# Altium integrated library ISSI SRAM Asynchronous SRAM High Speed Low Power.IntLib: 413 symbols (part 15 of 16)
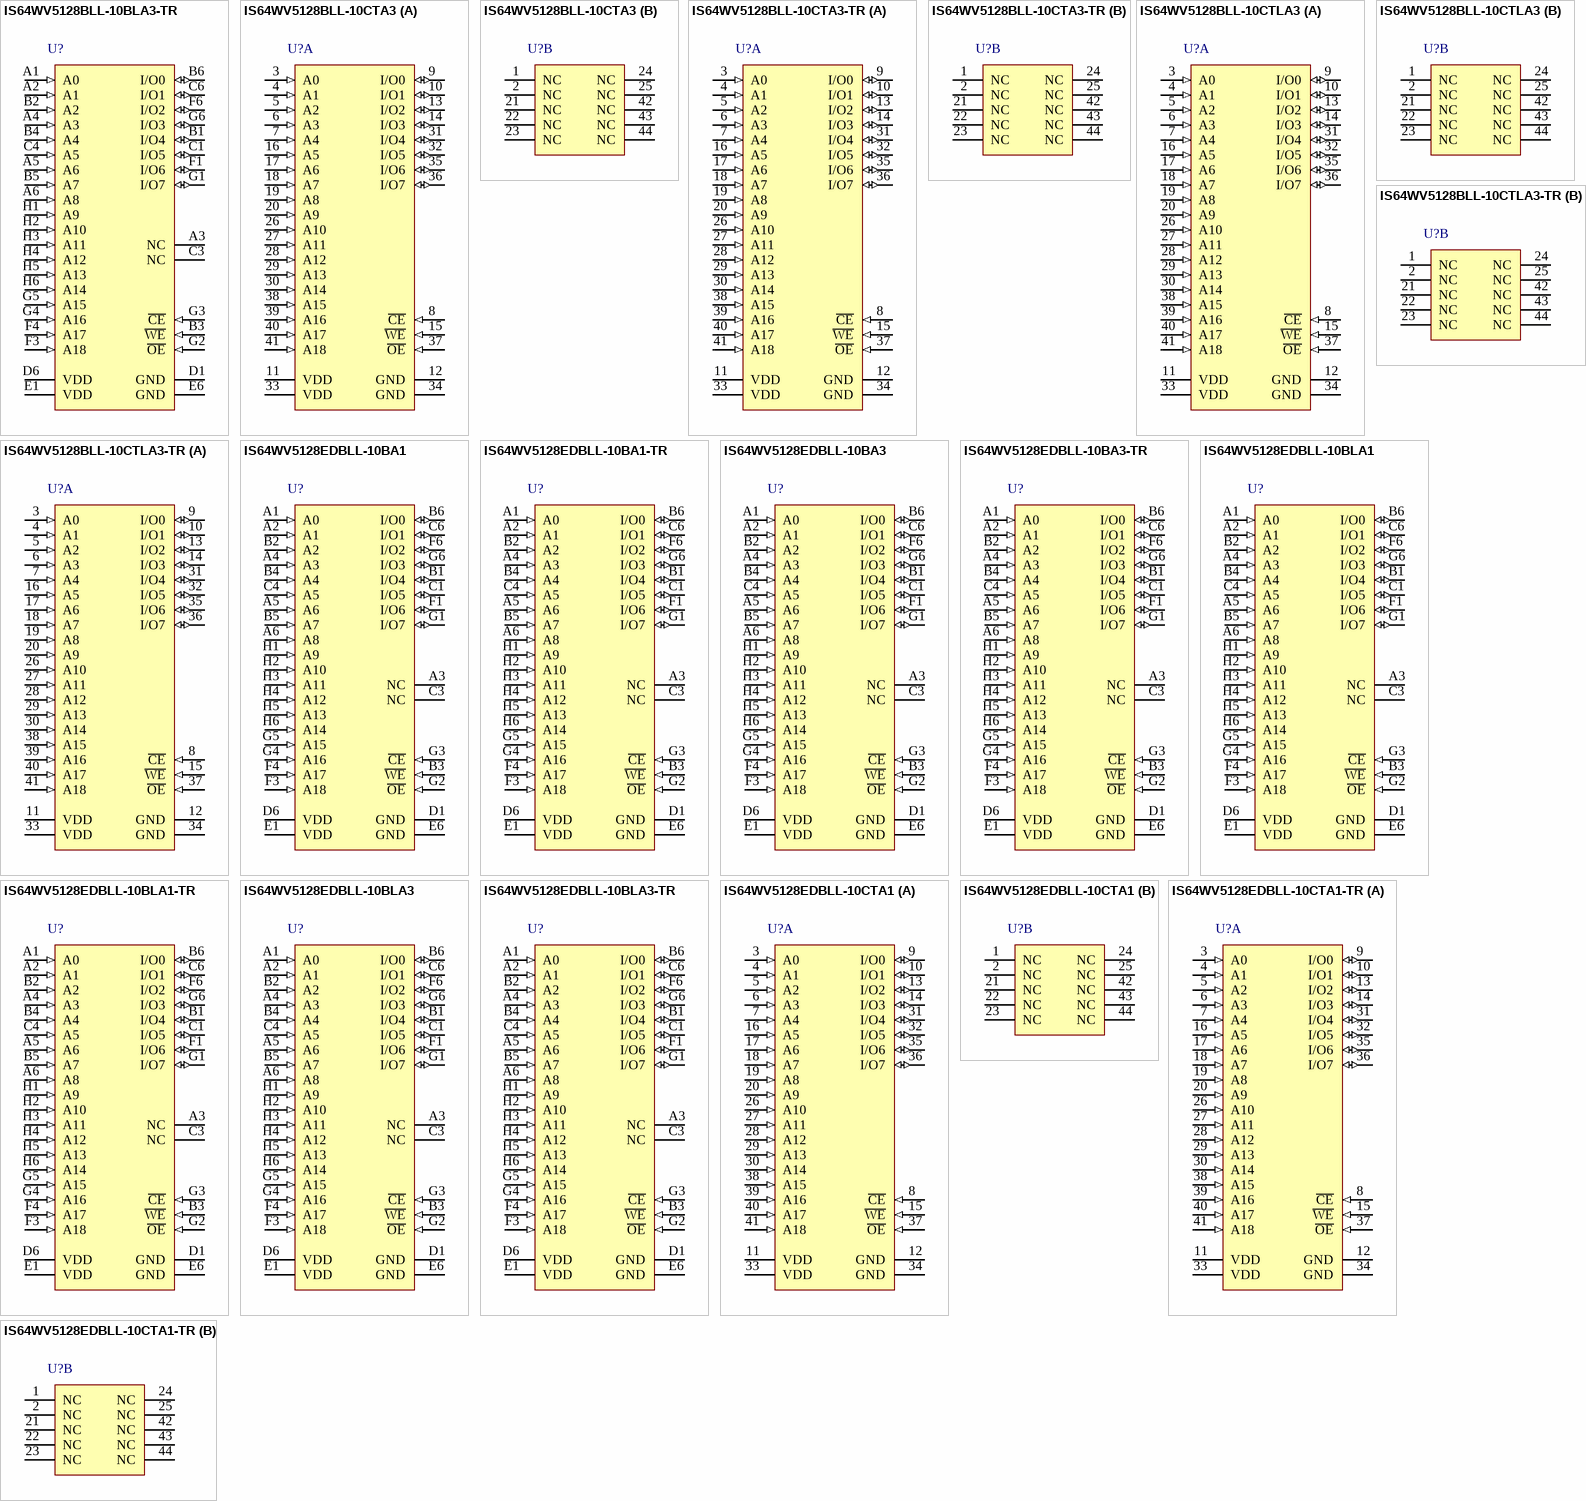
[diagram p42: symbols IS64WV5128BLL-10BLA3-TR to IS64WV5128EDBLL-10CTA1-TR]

## IS64WV5128BLL-10CTLA3-TR
designator U?
4 M High Speed Asynchronous CMOS SRAM, 512 K x 8, -40 to 125 degC, 44-Pin SOP (TSOP-2-44), Pb-Free; Manufacturer: Integrated Silicon Solution Inc (ISSI); PartNumber: IS64WV5128BLL-10CTLA3-TR; Density: 4M; Organization: 512K x 8; Packing: Tape & Reel; Speed (ns): 10
footprint ISSI-TSOP-2-44_N (SOP, 44-Leads, Body 18.5x10.3mm, Pitch 0.8mm, IPC Medium Density)
part A pins: 3 A0 (in) "Address Input", 4 A1 (in) "Address Input", 5 A2 (in) "Address Input", 6 A3 (in) "Address Input", 7 A4 (in) "Address Input", 8 ~{CE} (in) "Chip Enable Input", 9 I/O0 (io) "Bidirectional Port", 10 I/O1 (io) "Bidirectional Port", 11 VDD (power) "Power", 12 GND (power) "Ground", 13 I/O2 (io) "Bidirectional Port", 14 I/O3 (io) "Bidirectional Port", 15 ~{WE} (in) "Write Enable Input", 16 A5 (in) "Address Input", 17 A6 (in) "Address Input", 18 A7 (in) "Address Input", 19 A8 (in) "Address Input", 20 A9 (in) "Address Input", 26 A10 (in) "Address Input", 27 A11 (in) "Address Input", 28 A12 (in) "Address Input", 29 A13 (in) "Address Input", 30 A14 (in) "Address Input", 31 I/O4 (io) "Bidirectional Port", 32 I/O5 (io) "Bidirectional Port", 33 VDD (power) "Power", 34 GND (power) "Ground", 35 I/O6 (io) "Bidirectional Port", 36 I/O7 (io) "Bidirectional Port", 37 ~{OE} (in) "Output Enable Input", 38 A15 (in) "Address Input", 39 A16 (in) "Address Input", 40 A17 (in) "Address Input", 41 A18 (in) "Address Input"
part B pins: 1 NC "No Connection", 2 NC "No Connection", 21 NC "No Connection", 22 NC "No Connection", 23 NC "No Connection", 24 NC "No Connection", 25 NC "No Connection", 42 NC "No Connection", 43 NC "No Connection", 44 NC "No Connection"

## IS64WV5128EDBLL-10BA1
designator U?
4 M High Speed Asynchronous CMOS SRAM with ECC, 512 K x 8, -40 to 85 degC, 36-Pin BGA (TF-BGA-36); Manufacturer: Integrated Silicon Solution Inc (ISSI); PartNumber: IS64WV5128EDBLL-10BA1; Density: 4M; Organization: 512K x 8; Packing: Tray / Tube; Speed (ns): 10
footprint ISSI-TF-BGA-36-6000x8000DE (BGA, 36-Balls, Body 8x6mm, Pitch 0.75mm)
pins: A1 A0 (in) "Address Input", A2 A1 (in) "Address Input", A3 NC "No Connection", A4 A3 (in) "Address Input", A5 A6 (in) "Address Input", A6 A8 (in) "Address Input", B1 I/O4 (io) "Bidirectional Port", B2 A2 (in) "Address Input", B3 ~{WE} (in) "Write Enable Input", B4 A4 (in) "Address Input", B5 A7 (in) "Address Input", B6 I/O0 (io) "Bidirectional Port", C1 I/O5 (io) "Bidirectional Port", C3 NC "No Connection", C4 A5 (in) "Address Input", C6 I/O1 (io) "Bidirectional Port", D1 GND (power) "Ground", D6 VDD (power) "Power", E1 VDD (power) "Power", E6 GND (power) "Ground", F1 I/O6 (io) "Bidirectional Port", F3 A18 (in) "Address Input", F4 A17 (in) "Address Input", F6 I/O2 (io) "Bidirectional Port", G1 I/O7 (io) "Bidirectional Port", G2 ~{OE} (in) "Output Enable Input", G3 ~{CE} (in) "Chip Enable Input", G4 A16 (in) "Address Input", G5 A15 (in) "Address Input", G6 I/O3 (io) "Bidirectional Port", H1 A9 (in) "Address Input", H2 A10 (in) "Address Input", H3 A11 (in) "Address Input", H4 A12 (in) "Address Input", H5 A13 (in) "Address Input", H6 A14 (in) "Address Input"

## IS64WV5128EDBLL-10BA1-TR
designator U?
4 M High Speed Asynchronous CMOS SRAM with ECC, 512 K x 8, -40 to 85 degC, 36-Pin BGA (TF-BGA-36); Manufacturer: Integrated Silicon Solution Inc (ISSI); PartNumber: IS64WV5128EDBLL-10BA1-TR; Density: 4M; Organization: 512K x 8; Packing: Tape & Reel; Speed (ns): 10
footprint ISSI-TF-BGA-36-6000x8000DE (BGA, 36-Balls, Body 8x6mm, Pitch 0.75mm)
pins: A1 A0 (in) "Address Input", A2 A1 (in) "Address Input", A3 NC "No Connection", A4 A3 (in) "Address Input", A5 A6 (in) "Address Input", A6 A8 (in) "Address Input", B1 I/O4 (io) "Bidirectional Port", B2 A2 (in) "Address Input", B3 ~{WE} (in) "Write Enable Input", B4 A4 (in) "Address Input", B5 A7 (in) "Address Input", B6 I/O0 (io) "Bidirectional Port", C1 I/O5 (io) "Bidirectional Port", C3 NC "No Connection", C4 A5 (in) "Address Input", C6 I/O1 (io) "Bidirectional Port", D1 GND (power) "Ground", D6 VDD (power) "Power", E1 VDD (power) "Power", E6 GND (power) "Ground", F1 I/O6 (io) "Bidirectional Port", F3 A18 (in) "Address Input", F4 A17 (in) "Address Input", F6 I/O2 (io) "Bidirectional Port", G1 I/O7 (io) "Bidirectional Port", G2 ~{OE} (in) "Output Enable Input", G3 ~{CE} (in) "Chip Enable Input", G4 A16 (in) "Address Input", G5 A15 (in) "Address Input", G6 I/O3 (io) "Bidirectional Port", H1 A9 (in) "Address Input", H2 A10 (in) "Address Input", H3 A11 (in) "Address Input", H4 A12 (in) "Address Input", H5 A13 (in) "Address Input", H6 A14 (in) "Address Input"

## IS64WV5128EDBLL-10BA3
designator U?
4 M High Speed Asynchronous CMOS SRAM with ECC, 512 K x 8, -40 to 125 degC, 36-Pin BGA (TF-BGA-36); Manufacturer: Integrated Silicon Solution Inc (ISSI); PartNumber: IS64WV5128EDBLL-10BA3; Density: 4M; Organization: 512K x 8; Packing: Tray / Tube; Speed (ns): 10
footprint ISSI-TF-BGA-36-6000x8000DE (BGA, 36-Balls, Body 8x6mm, Pitch 0.75mm)
pins: A1 A0 (in) "Address Input", A2 A1 (in) "Address Input", A3 NC "No Connection", A4 A3 (in) "Address Input", A5 A6 (in) "Address Input", A6 A8 (in) "Address Input", B1 I/O4 (io) "Bidirectional Port", B2 A2 (in) "Address Input", B3 ~{WE} (in) "Write Enable Input", B4 A4 (in) "Address Input", B5 A7 (in) "Address Input", B6 I/O0 (io) "Bidirectional Port", C1 I/O5 (io) "Bidirectional Port", C3 NC "No Connection", C4 A5 (in) "Address Input", C6 I/O1 (io) "Bidirectional Port", D1 GND (power) "Ground", D6 VDD (power) "Power", E1 VDD (power) "Power", E6 GND (power) "Ground", F1 I/O6 (io) "Bidirectional Port", F3 A18 (in) "Address Input", F4 A17 (in) "Address Input", F6 I/O2 (io) "Bidirectional Port", G1 I/O7 (io) "Bidirectional Port", G2 ~{OE} (in) "Output Enable Input", G3 ~{CE} (in) "Chip Enable Input", G4 A16 (in) "Address Input", G5 A15 (in) "Address Input", G6 I/O3 (io) "Bidirectional Port", H1 A9 (in) "Address Input", H2 A10 (in) "Address Input", H3 A11 (in) "Address Input", H4 A12 (in) "Address Input", H5 A13 (in) "Address Input", H6 A14 (in) "Address Input"

## IS64WV5128EDBLL-10BA3-TR
designator U?
4 M High Speed Asynchronous CMOS SRAM with ECC, 512 K x 8, -40 to 125 degC, 36-Pin BGA (TF-BGA-36); Manufacturer: Integrated Silicon Solution Inc (ISSI); PartNumber: IS64WV5128EDBLL-10BA3-TR; Density: 4M; Organization: 512K x 8; Packing: Tape & Reel; Speed (ns): 10
footprint ISSI-TF-BGA-36-6000x8000DE (BGA, 36-Balls, Body 8x6mm, Pitch 0.75mm)
pins: A1 A0 (in) "Address Input", A2 A1 (in) "Address Input", A3 NC "No Connection", A4 A3 (in) "Address Input", A5 A6 (in) "Address Input", A6 A8 (in) "Address Input", B1 I/O4 (io) "Bidirectional Port", B2 A2 (in) "Address Input", B3 ~{WE} (in) "Write Enable Input", B4 A4 (in) "Address Input", B5 A7 (in) "Address Input", B6 I/O0 (io) "Bidirectional Port", C1 I/O5 (io) "Bidirectional Port", C3 NC "No Connection", C4 A5 (in) "Address Input", C6 I/O1 (io) "Bidirectional Port", D1 GND (power) "Ground", D6 VDD (power) "Power", E1 VDD (power) "Power", E6 GND (power) "Ground", F1 I/O6 (io) "Bidirectional Port", F3 A18 (in) "Address Input", F4 A17 (in) "Address Input", F6 I/O2 (io) "Bidirectional Port", G1 I/O7 (io) "Bidirectional Port", G2 ~{OE} (in) "Output Enable Input", G3 ~{CE} (in) "Chip Enable Input", G4 A16 (in) "Address Input", G5 A15 (in) "Address Input", G6 I/O3 (io) "Bidirectional Port", H1 A9 (in) "Address Input", H2 A10 (in) "Address Input", H3 A11 (in) "Address Input", H4 A12 (in) "Address Input", H5 A13 (in) "Address Input", H6 A14 (in) "Address Input"

## IS64WV5128EDBLL-10BLA1
designator U?
4 M High Speed Asynchronous CMOS SRAM with ECC, 512 K x 8, -40 to 85 degC, 36-Pin BGA (TF-BGA-36), Pb-Free; Manufacturer: Integrated Silicon Solution Inc (ISSI); PartNumber: IS64WV5128EDBLL-10BLA1; Density: 4M; Organization: 512K x 8; Packing: Tray / Tube; Speed (ns): 10
footprint ISSI-TF-BGA-36-6000x8000DE (BGA, 36-Balls, Body 8x6mm, Pitch 0.75mm)
pins: A1 A0 (in) "Address Input", A2 A1 (in) "Address Input", A3 NC "No Connection", A4 A3 (in) "Address Input", A5 A6 (in) "Address Input", A6 A8 (in) "Address Input", B1 I/O4 (io) "Bidirectional Port", B2 A2 (in) "Address Input", B3 ~{WE} (in) "Write Enable Input", B4 A4 (in) "Address Input", B5 A7 (in) "Address Input", B6 I/O0 (io) "Bidirectional Port", C1 I/O5 (io) "Bidirectional Port", C3 NC "No Connection", C4 A5 (in) "Address Input", C6 I/O1 (io) "Bidirectional Port", D1 GND (power) "Ground", D6 VDD (power) "Power", E1 VDD (power) "Power", E6 GND (power) "Ground", F1 I/O6 (io) "Bidirectional Port", F3 A18 (in) "Address Input", F4 A17 (in) "Address Input", F6 I/O2 (io) "Bidirectional Port", G1 I/O7 (io) "Bidirectional Port", G2 ~{OE} (in) "Output Enable Input", G3 ~{CE} (in) "Chip Enable Input", G4 A16 (in) "Address Input", G5 A15 (in) "Address Input", G6 I/O3 (io) "Bidirectional Port", H1 A9 (in) "Address Input", H2 A10 (in) "Address Input", H3 A11 (in) "Address Input", H4 A12 (in) "Address Input", H5 A13 (in) "Address Input", H6 A14 (in) "Address Input"

## IS64WV5128EDBLL-10BLA1-TR
designator U?
4 M High Speed Asynchronous CMOS SRAM with ECC, 512 K x 8, -40 to 85 degC, 36-Pin BGA (TF-BGA-36), Pb-Free; Manufacturer: Integrated Silicon Solution Inc (ISSI); PartNumber: IS64WV5128EDBLL-10BLA1-TR; Density: 4M; Organization: 512K x 8; Packing: Tape & Reel; Speed (ns): 10
footprint ISSI-TF-BGA-36-6000x8000DE (BGA, 36-Balls, Body 8x6mm, Pitch 0.75mm)
pins: A1 A0 (in) "Address Input", A2 A1 (in) "Address Input", A3 NC "No Connection", A4 A3 (in) "Address Input", A5 A6 (in) "Address Input", A6 A8 (in) "Address Input", B1 I/O4 (io) "Bidirectional Port", B2 A2 (in) "Address Input", B3 ~{WE} (in) "Write Enable Input", B4 A4 (in) "Address Input", B5 A7 (in) "Address Input", B6 I/O0 (io) "Bidirectional Port", C1 I/O5 (io) "Bidirectional Port", C3 NC "No Connection", C4 A5 (in) "Address Input", C6 I/O1 (io) "Bidirectional Port", D1 GND (power) "Ground", D6 VDD (power) "Power", E1 VDD (power) "Power", E6 GND (power) "Ground", F1 I/O6 (io) "Bidirectional Port", F3 A18 (in) "Address Input", F4 A17 (in) "Address Input", F6 I/O2 (io) "Bidirectional Port", G1 I/O7 (io) "Bidirectional Port", G2 ~{OE} (in) "Output Enable Input", G3 ~{CE} (in) "Chip Enable Input", G4 A16 (in) "Address Input", G5 A15 (in) "Address Input", G6 I/O3 (io) "Bidirectional Port", H1 A9 (in) "Address Input", H2 A10 (in) "Address Input", H3 A11 (in) "Address Input", H4 A12 (in) "Address Input", H5 A13 (in) "Address Input", H6 A14 (in) "Address Input"

## IS64WV5128EDBLL-10BLA3
designator U?
4 M High Speed Asynchronous CMOS SRAM with ECC, 512 K x 8, -40 to 125 degC, 36-Pin BGA (TF-BGA-36), Pb-Free; Manufacturer: Integrated Silicon Solution Inc (ISSI); PartNumber: IS64WV5128EDBLL-10BLA3; Density: 4M; Organization: 512K x 8; Packing: Tray / Tube; Speed (ns): 10
footprint ISSI-TF-BGA-36-6000x8000DE (BGA, 36-Balls, Body 8x6mm, Pitch 0.75mm)
pins: A1 A0 (in) "Address Input", A2 A1 (in) "Address Input", A3 NC "No Connection", A4 A3 (in) "Address Input", A5 A6 (in) "Address Input", A6 A8 (in) "Address Input", B1 I/O4 (io) "Bidirectional Port", B2 A2 (in) "Address Input", B3 ~{WE} (in) "Write Enable Input", B4 A4 (in) "Address Input", B5 A7 (in) "Address Input", B6 I/O0 (io) "Bidirectional Port", C1 I/O5 (io) "Bidirectional Port", C3 NC "No Connection", C4 A5 (in) "Address Input", C6 I/O1 (io) "Bidirectional Port", D1 GND (power) "Ground", D6 VDD (power) "Power", E1 VDD (power) "Power", E6 GND (power) "Ground", F1 I/O6 (io) "Bidirectional Port", F3 A18 (in) "Address Input", F4 A17 (in) "Address Input", F6 I/O2 (io) "Bidirectional Port", G1 I/O7 (io) "Bidirectional Port", G2 ~{OE} (in) "Output Enable Input", G3 ~{CE} (in) "Chip Enable Input", G4 A16 (in) "Address Input", G5 A15 (in) "Address Input", G6 I/O3 (io) "Bidirectional Port", H1 A9 (in) "Address Input", H2 A10 (in) "Address Input", H3 A11 (in) "Address Input", H4 A12 (in) "Address Input", H5 A13 (in) "Address Input", H6 A14 (in) "Address Input"

## IS64WV5128EDBLL-10BLA3-TR
designator U?
4 M High Speed Asynchronous CMOS SRAM with ECC, 512 K x 8, -40 to 125 degC, 36-Pin BGA (TF-BGA-36), Pb-Free; Manufacturer: Integrated Silicon Solution Inc (ISSI); PartNumber: IS64WV5128EDBLL-10BLA3-TR; Density: 4M; Organization: 512K x 8; Packing: Tape & Reel; Speed (ns): 10
footprint ISSI-TF-BGA-36-6000x8000DE (BGA, 36-Balls, Body 8x6mm, Pitch 0.75mm)
pins: A1 A0 (in) "Address Input", A2 A1 (in) "Address Input", A3 NC "No Connection", A4 A3 (in) "Address Input", A5 A6 (in) "Address Input", A6 A8 (in) "Address Input", B1 I/O4 (io) "Bidirectional Port", B2 A2 (in) "Address Input", B3 ~{WE} (in) "Write Enable Input", B4 A4 (in) "Address Input", B5 A7 (in) "Address Input", B6 I/O0 (io) "Bidirectional Port", C1 I/O5 (io) "Bidirectional Port", C3 NC "No Connection", C4 A5 (in) "Address Input", C6 I/O1 (io) "Bidirectional Port", D1 GND (power) "Ground", D6 VDD (power) "Power", E1 VDD (power) "Power", E6 GND (power) "Ground", F1 I/O6 (io) "Bidirectional Port", F3 A18 (in) "Address Input", F4 A17 (in) "Address Input", F6 I/O2 (io) "Bidirectional Port", G1 I/O7 (io) "Bidirectional Port", G2 ~{OE} (in) "Output Enable Input", G3 ~{CE} (in) "Chip Enable Input", G4 A16 (in) "Address Input", G5 A15 (in) "Address Input", G6 I/O3 (io) "Bidirectional Port", H1 A9 (in) "Address Input", H2 A10 (in) "Address Input", H3 A11 (in) "Address Input", H4 A12 (in) "Address Input", H5 A13 (in) "Address Input", H6 A14 (in) "Address Input"

## IS64WV5128EDBLL-10CTA1
designator U?
4 M High Speed Asynchronous CMOS SRAM with ECC, 512 K x 8, -40 to 85 degC, 44-Pin SOP (TSOP-2-44); Manufacturer: Integrated Silicon Solution Inc (ISSI); PartNumber: IS64WV5128EDBLL-10CTA1; Density: 4M; Organization: 512K x 8; Packing: Tray / Tube; Speed (ns): 10
footprint ISSI-TSOP-2-44_N (SOP, 44-Leads, Body 18.5x10.3mm, Pitch 0.8mm, IPC Medium Density)
part A pins: 3 A0 (in) "Address Input", 4 A1 (in) "Address Input", 5 A2 (in) "Address Input", 6 A3 (in) "Address Input", 7 A4 (in) "Address Input", 8 ~{CE} (in) "Chip Enable Input", 9 I/O0 (io) "Bidirectional Port", 10 I/O1 (io) "Bidirectional Port", 11 VDD (power) "Power", 12 GND (power) "Ground", 13 I/O2 (io) "Bidirectional Port", 14 I/O3 (io) "Bidirectional Port", 15 ~{WE} (in) "Write Enable Input", 16 A5 (in) "Address Input", 17 A6 (in) "Address Input", 18 A7 (in) "Address Input", 19 A8 (in) "Address Input", 20 A9 (in) "Address Input", 26 A10 (in) "Address Input", 27 A11 (in) "Address Input", 28 A12 (in) "Address Input", 29 A13 (in) "Address Input", 30 A14 (in) "Address Input", 31 I/O4 (io) "Bidirectional Port", 32 I/O5 (io) "Bidirectional Port", 33 VDD (power) "Power", 34 GND (power) "Ground", 35 I/O6 (io) "Bidirectional Port", 36 I/O7 (io) "Bidirectional Port", 37 ~{OE} (in) "Output Enable Input", 38 A15 (in) "Address Input", 39 A16 (in) "Address Input", 40 A17 (in) "Address Input", 41 A18 (in) "Address Input"
part B pins: 1 NC "No Connection", 2 NC "No Connection", 21 NC "No Connection", 22 NC "No Connection", 23 NC "No Connection", 24 NC "No Connection", 25 NC "No Connection", 42 NC "No Connection", 43 NC "No Connection", 44 NC "No Connection"

## IS64WV5128EDBLL-10CTA1-TR
designator U?
4 M High Speed Asynchronous CMOS SRAM with ECC, 512 K x 8, -40 to 85 degC, 44-Pin SOP (TSOP-2-44); Manufacturer: Integrated Silicon Solution Inc (ISSI); PartNumber: IS64WV5128EDBLL-10CTA1-TR; Density: 4M; Organization: 512K x 8; Packing: Tape & Reel; Speed (ns): 10
footprint ISSI-TSOP-2-44_N (SOP, 44-Leads, Body 18.5x10.3mm, Pitch 0.8mm, IPC Medium Density)
part A pins: 3 A0 (in) "Address Input", 4 A1 (in) "Address Input", 5 A2 (in) "Address Input", 6 A3 (in) "Address Input", 7 A4 (in) "Address Input", 8 ~{CE} (in) "Chip Enable Input", 9 I/O0 (io) "Bidirectional Port", 10 I/O1 (io) "Bidirectional Port", 11 VDD (power) "Power", 12 GND (power) "Ground", 13 I/O2 (io) "Bidirectional Port", 14 I/O3 (io) "Bidirectional Port", 15 ~{WE} (in) "Write Enable Input", 16 A5 (in) "Address Input", 17 A6 (in) "Address Input", 18 A7 (in) "Address Input", 19 A8 (in) "Address Input", 20 A9 (in) "Address Input", 26 A10 (in) "Address Input", 27 A11 (in) "Address Input", 28 A12 (in) "Address Input", 29 A13 (in) "Address Input", 30 A14 (in) "Address Input", 31 I/O4 (io) "Bidirectional Port", 32 I/O5 (io) "Bidirectional Port", 33 VDD (power) "Power", 34 GND (power) "Ground", 35 I/O6 (io) "Bidirectional Port", 36 I/O7 (io) "Bidirectional Port", 37 ~{OE} (in) "Output Enable Input", 38 A15 (in) "Address Input", 39 A16 (in) "Address Input", 40 A17 (in) "Address Input", 41 A18 (in) "Address Input"
part B pins: 1 NC "No Connection", 2 NC "No Connection", 21 NC "No Connection", 22 NC "No Connection", 23 NC "No Connection", 24 NC "No Connection", 25 NC "No Connection", 42 NC "No Connection", 43 NC "No Connection", 44 NC "No Connection"

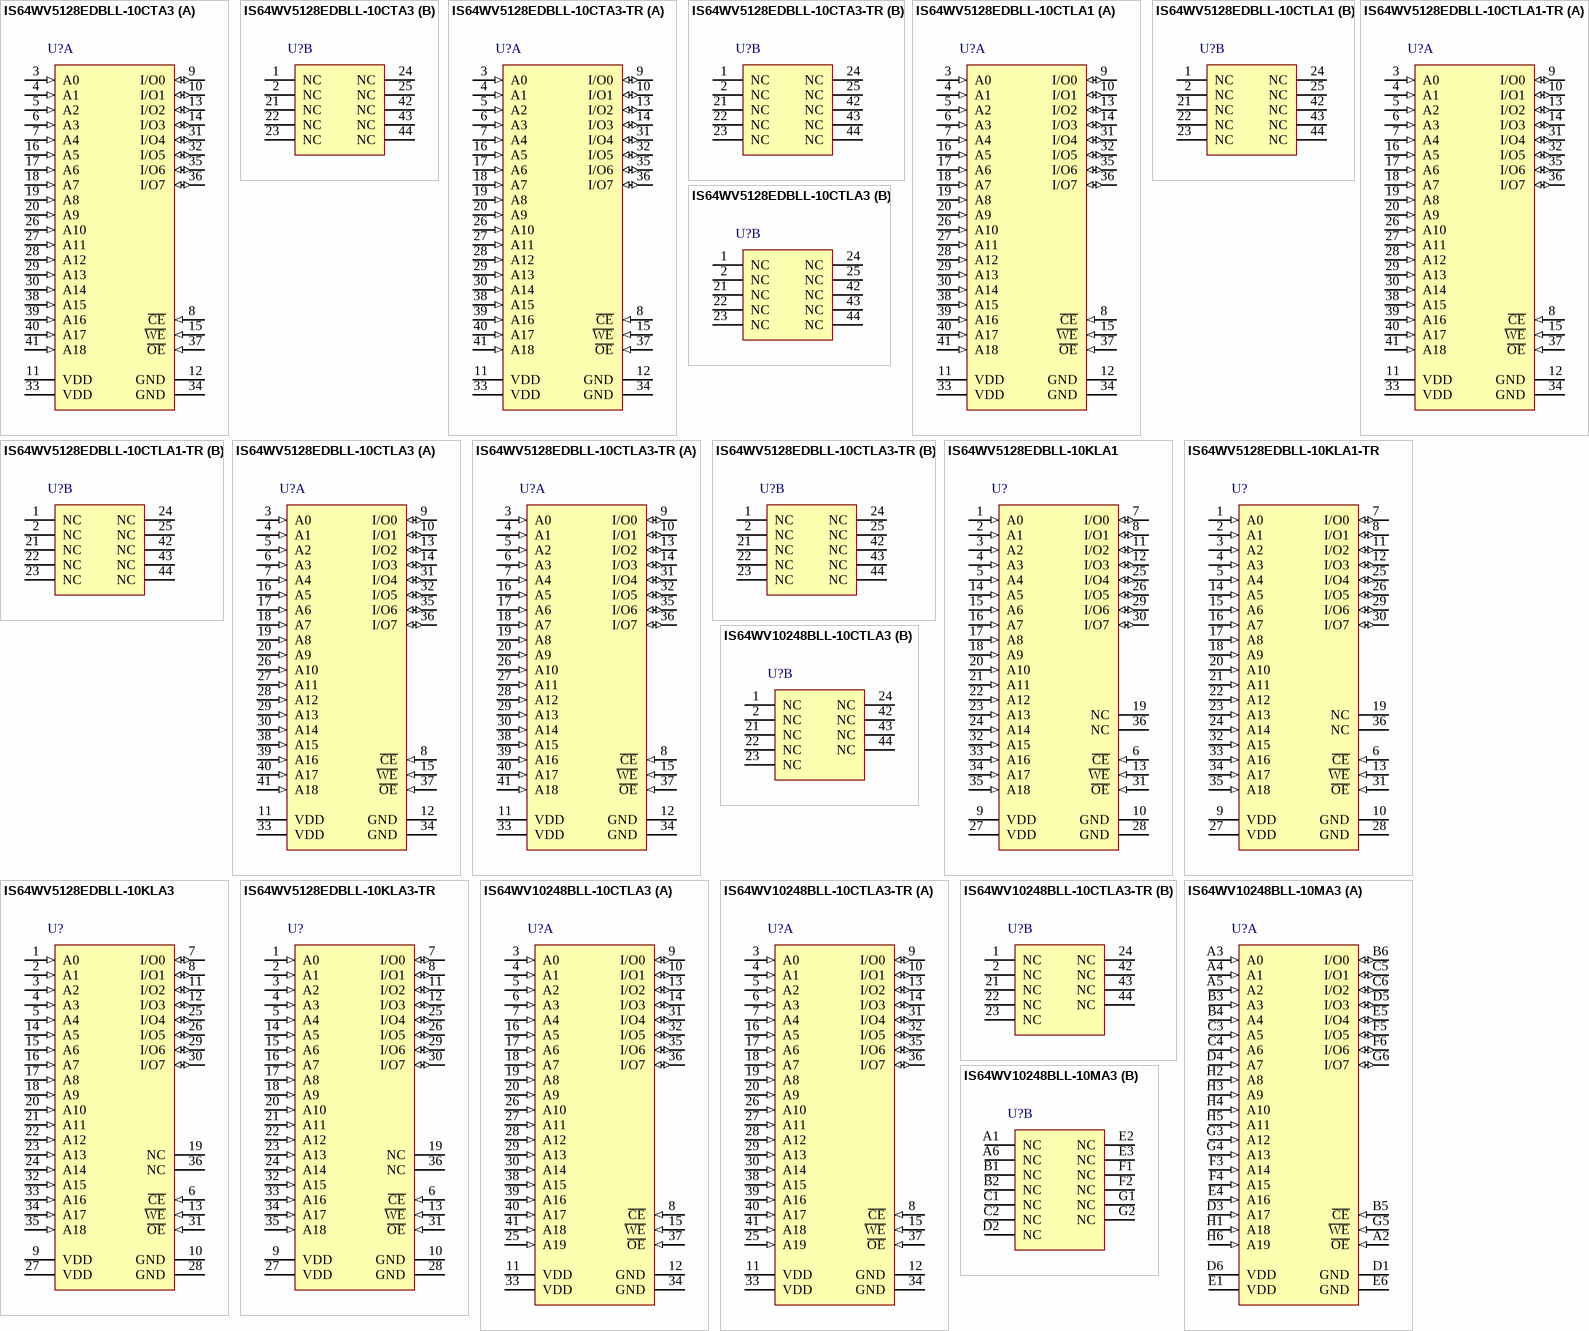
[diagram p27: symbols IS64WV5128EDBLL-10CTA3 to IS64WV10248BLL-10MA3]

## IS64WV5128EDBLL-10CTA3
designator U?
4 M High Speed Asynchronous CMOS SRAM with ECC, 512 K x 8, -40 to 125 degC, 44-Pin SOP (TSOP-2-44); Manufacturer: Integrated Silicon Solution Inc (ISSI); PartNumber: IS64WV5128EDBLL-10CTA3; Density: 4M; Organization: 512K x 8; Packing: Tray / Tube; Speed (ns): 10
footprint ISSI-TSOP-2-44_N (SOP, 44-Leads, Body 18.5x10.3mm, Pitch 0.8mm, IPC Medium Density)
part A pins: 3 A0 (in) "Address Input", 4 A1 (in) "Address Input", 5 A2 (in) "Address Input", 6 A3 (in) "Address Input", 7 A4 (in) "Address Input", 8 ~{CE} (in) "Chip Enable Input", 9 I/O0 (io) "Bidirectional Port", 10 I/O1 (io) "Bidirectional Port", 11 VDD (power) "Power", 12 GND (power) "Ground", 13 I/O2 (io) "Bidirectional Port", 14 I/O3 (io) "Bidirectional Port", 15 ~{WE} (in) "Write Enable Input", 16 A5 (in) "Address Input", 17 A6 (in) "Address Input", 18 A7 (in) "Address Input", 19 A8 (in) "Address Input", 20 A9 (in) "Address Input", 26 A10 (in) "Address Input", 27 A11 (in) "Address Input", 28 A12 (in) "Address Input", 29 A13 (in) "Address Input", 30 A14 (in) "Address Input", 31 I/O4 (io) "Bidirectional Port", 32 I/O5 (io) "Bidirectional Port", 33 VDD (power) "Power", 34 GND (power) "Ground", 35 I/O6 (io) "Bidirectional Port", 36 I/O7 (io) "Bidirectional Port", 37 ~{OE} (in) "Output Enable Input", 38 A15 (in) "Address Input", 39 A16 (in) "Address Input", 40 A17 (in) "Address Input", 41 A18 (in) "Address Input"
part B pins: 1 NC "No Connection", 2 NC "No Connection", 21 NC "No Connection", 22 NC "No Connection", 23 NC "No Connection", 24 NC "No Connection", 25 NC "No Connection", 42 NC "No Connection", 43 NC "No Connection", 44 NC "No Connection"

## IS64WV5128EDBLL-10CTA3-TR
designator U?
4 M High Speed Asynchronous CMOS SRAM with ECC, 512 K x 8, -40 to 125 degC, 44-Pin SOP (TSOP-2-44); Manufacturer: Integrated Silicon Solution Inc (ISSI); PartNumber: IS64WV5128EDBLL-10CTA3-TR; Density: 4M; Organization: 512K x 8; Packing: Tape & Reel; Speed (ns): 10
footprint ISSI-TSOP-2-44_N (SOP, 44-Leads, Body 18.5x10.3mm, Pitch 0.8mm, IPC Medium Density)
part A pins: 3 A0 (in) "Address Input", 4 A1 (in) "Address Input", 5 A2 (in) "Address Input", 6 A3 (in) "Address Input", 7 A4 (in) "Address Input", 8 ~{CE} (in) "Chip Enable Input", 9 I/O0 (io) "Bidirectional Port", 10 I/O1 (io) "Bidirectional Port", 11 VDD (power) "Power", 12 GND (power) "Ground", 13 I/O2 (io) "Bidirectional Port", 14 I/O3 (io) "Bidirectional Port", 15 ~{WE} (in) "Write Enable Input", 16 A5 (in) "Address Input", 17 A6 (in) "Address Input", 18 A7 (in) "Address Input", 19 A8 (in) "Address Input", 20 A9 (in) "Address Input", 26 A10 (in) "Address Input", 27 A11 (in) "Address Input", 28 A12 (in) "Address Input", 29 A13 (in) "Address Input", 30 A14 (in) "Address Input", 31 I/O4 (io) "Bidirectional Port", 32 I/O5 (io) "Bidirectional Port", 33 VDD (power) "Power", 34 GND (power) "Ground", 35 I/O6 (io) "Bidirectional Port", 36 I/O7 (io) "Bidirectional Port", 37 ~{OE} (in) "Output Enable Input", 38 A15 (in) "Address Input", 39 A16 (in) "Address Input", 40 A17 (in) "Address Input", 41 A18 (in) "Address Input"
part B pins: 1 NC "No Connection", 2 NC "No Connection", 21 NC "No Connection", 22 NC "No Connection", 23 NC "No Connection", 24 NC "No Connection", 25 NC "No Connection", 42 NC "No Connection", 43 NC "No Connection", 44 NC "No Connection"

## IS64WV5128EDBLL-10CTLA1
designator U?
4 M High Speed Asynchronous CMOS SRAM with ECC, 512 K x 8, -40 to 85 degC, 44-Pin SOP (TSOP-2-44), Pb-Free; Manufacturer: Integrated Silicon Solution Inc (ISSI); PartNumber: IS64WV5128EDBLL-10CTLA1; Density: 4M; Organization: 512K x 8; Packing: Tray / Tube; Speed (ns): 10
footprint ISSI-TSOP-2-44_N (SOP, 44-Leads, Body 18.5x10.3mm, Pitch 0.8mm, IPC Medium Density)
part A pins: 3 A0 (in) "Address Input", 4 A1 (in) "Address Input", 5 A2 (in) "Address Input", 6 A3 (in) "Address Input", 7 A4 (in) "Address Input", 8 ~{CE} (in) "Chip Enable Input", 9 I/O0 (io) "Bidirectional Port", 10 I/O1 (io) "Bidirectional Port", 11 VDD (power) "Power", 12 GND (power) "Ground", 13 I/O2 (io) "Bidirectional Port", 14 I/O3 (io) "Bidirectional Port", 15 ~{WE} (in) "Write Enable Input", 16 A5 (in) "Address Input", 17 A6 (in) "Address Input", 18 A7 (in) "Address Input", 19 A8 (in) "Address Input", 20 A9 (in) "Address Input", 26 A10 (in) "Address Input", 27 A11 (in) "Address Input", 28 A12 (in) "Address Input", 29 A13 (in) "Address Input", 30 A14 (in) "Address Input", 31 I/O4 (io) "Bidirectional Port", 32 I/O5 (io) "Bidirectional Port", 33 VDD (power) "Power", 34 GND (power) "Ground", 35 I/O6 (io) "Bidirectional Port", 36 I/O7 (io) "Bidirectional Port", 37 ~{OE} (in) "Output Enable Input", 38 A15 (in) "Address Input", 39 A16 (in) "Address Input", 40 A17 (in) "Address Input", 41 A18 (in) "Address Input"
part B pins: 1 NC "No Connection", 2 NC "No Connection", 21 NC "No Connection", 22 NC "No Connection", 23 NC "No Connection", 24 NC "No Connection", 25 NC "No Connection", 42 NC "No Connection", 43 NC "No Connection", 44 NC "No Connection"

## IS64WV5128EDBLL-10CTLA1-TR
designator U?
4 M High Speed Asynchronous CMOS SRAM with ECC, 512 K x 8, -40 to 85 degC, 44-Pin SOP (TSOP-2-44), Pb-Free; Manufacturer: Integrated Silicon Solution Inc (ISSI); PartNumber: IS64WV5128EDBLL-10CTLA1-TR; Density: 4M; Organization: 512K x 8; Packing: Tape & Reel; Speed (ns): 10
footprint ISSI-TSOP-2-44_N (SOP, 44-Leads, Body 18.5x10.3mm, Pitch 0.8mm, IPC Medium Density)
part A pins: 3 A0 (in) "Address Input", 4 A1 (in) "Address Input", 5 A2 (in) "Address Input", 6 A3 (in) "Address Input", 7 A4 (in) "Address Input", 8 ~{CE} (in) "Chip Enable Input", 9 I/O0 (io) "Bidirectional Port", 10 I/O1 (io) "Bidirectional Port", 11 VDD (power) "Power", 12 GND (power) "Ground", 13 I/O2 (io) "Bidirectional Port", 14 I/O3 (io) "Bidirectional Port", 15 ~{WE} (in) "Write Enable Input", 16 A5 (in) "Address Input", 17 A6 (in) "Address Input", 18 A7 (in) "Address Input", 19 A8 (in) "Address Input", 20 A9 (in) "Address Input", 26 A10 (in) "Address Input", 27 A11 (in) "Address Input", 28 A12 (in) "Address Input", 29 A13 (in) "Address Input", 30 A14 (in) "Address Input", 31 I/O4 (io) "Bidirectional Port", 32 I/O5 (io) "Bidirectional Port", 33 VDD (power) "Power", 34 GND (power) "Ground", 35 I/O6 (io) "Bidirectional Port", 36 I/O7 (io) "Bidirectional Port", 37 ~{OE} (in) "Output Enable Input", 38 A15 (in) "Address Input", 39 A16 (in) "Address Input", 40 A17 (in) "Address Input", 41 A18 (in) "Address Input"
part B pins: 1 NC "No Connection", 2 NC "No Connection", 21 NC "No Connection", 22 NC "No Connection", 23 NC "No Connection", 24 NC "No Connection", 25 NC "No Connection", 42 NC "No Connection", 43 NC "No Connection", 44 NC "No Connection"

## IS64WV5128EDBLL-10CTLA3
designator U?
4 M High Speed Asynchronous CMOS SRAM with ECC, 512 K x 8, -40 to 125 degC, 44-Pin SOP (TSOP-2-44), Pb-Free; Manufacturer: Integrated Silicon Solution Inc (ISSI); PartNumber: IS64WV5128EDBLL-10CTLA3; Density: 4M; Organization: 512K x 8; Packing: Tray / Tube; Speed (ns): 10
footprint ISSI-TSOP-2-44_N (SOP, 44-Leads, Body 18.5x10.3mm, Pitch 0.8mm, IPC Medium Density)
part A pins: 3 A0 (in) "Address Input", 4 A1 (in) "Address Input", 5 A2 (in) "Address Input", 6 A3 (in) "Address Input", 7 A4 (in) "Address Input", 8 ~{CE} (in) "Chip Enable Input", 9 I/O0 (io) "Bidirectional Port", 10 I/O1 (io) "Bidirectional Port", 11 VDD (power) "Power", 12 GND (power) "Ground", 13 I/O2 (io) "Bidirectional Port", 14 I/O3 (io) "Bidirectional Port", 15 ~{WE} (in) "Write Enable Input", 16 A5 (in) "Address Input", 17 A6 (in) "Address Input", 18 A7 (in) "Address Input", 19 A8 (in) "Address Input", 20 A9 (in) "Address Input", 26 A10 (in) "Address Input", 27 A11 (in) "Address Input", 28 A12 (in) "Address Input", 29 A13 (in) "Address Input", 30 A14 (in) "Address Input", 31 I/O4 (io) "Bidirectional Port", 32 I/O5 (io) "Bidirectional Port", 33 VDD (power) "Power", 34 GND (power) "Ground", 35 I/O6 (io) "Bidirectional Port", 36 I/O7 (io) "Bidirectional Port", 37 ~{OE} (in) "Output Enable Input", 38 A15 (in) "Address Input", 39 A16 (in) "Address Input", 40 A17 (in) "Address Input", 41 A18 (in) "Address Input"
part B pins: 1 NC "No Connection", 2 NC "No Connection", 21 NC "No Connection", 22 NC "No Connection", 23 NC "No Connection", 24 NC "No Connection", 25 NC "No Connection", 42 NC "No Connection", 43 NC "No Connection", 44 NC "No Connection"

## IS64WV5128EDBLL-10CTLA3-TR
designator U?
4 M High Speed Asynchronous CMOS SRAM with ECC, 512 K x 8, -40 to 125 degC, 44-Pin SOP (TSOP-2-44), Pb-Free; Manufacturer: Integrated Silicon Solution Inc (ISSI); PartNumber: IS64WV5128EDBLL-10CTLA3-TR; Density: 4M; Organization: 512K x 8; Packing: Tape & Reel; Speed (ns): 10
footprint ISSI-TSOP-2-44_N (SOP, 44-Leads, Body 18.5x10.3mm, Pitch 0.8mm, IPC Medium Density)
part A pins: 3 A0 (in) "Address Input", 4 A1 (in) "Address Input", 5 A2 (in) "Address Input", 6 A3 (in) "Address Input", 7 A4 (in) "Address Input", 8 ~{CE} (in) "Chip Enable Input", 9 I/O0 (io) "Bidirectional Port", 10 I/O1 (io) "Bidirectional Port", 11 VDD (power) "Power", 12 GND (power) "Ground", 13 I/O2 (io) "Bidirectional Port", 14 I/O3 (io) "Bidirectional Port", 15 ~{WE} (in) "Write Enable Input", 16 A5 (in) "Address Input", 17 A6 (in) "Address Input", 18 A7 (in) "Address Input", 19 A8 (in) "Address Input", 20 A9 (in) "Address Input", 26 A10 (in) "Address Input", 27 A11 (in) "Address Input", 28 A12 (in) "Address Input", 29 A13 (in) "Address Input", 30 A14 (in) "Address Input", 31 I/O4 (io) "Bidirectional Port", 32 I/O5 (io) "Bidirectional Port", 33 VDD (power) "Power", 34 GND (power) "Ground", 35 I/O6 (io) "Bidirectional Port", 36 I/O7 (io) "Bidirectional Port", 37 ~{OE} (in) "Output Enable Input", 38 A15 (in) "Address Input", 39 A16 (in) "Address Input", 40 A17 (in) "Address Input", 41 A18 (in) "Address Input"
part B pins: 1 NC "No Connection", 2 NC "No Connection", 21 NC "No Connection", 22 NC "No Connection", 23 NC "No Connection", 24 NC "No Connection", 25 NC "No Connection", 42 NC "No Connection", 43 NC "No Connection", 44 NC "No Connection"

## IS64WV5128EDBLL-10KLA1
designator U?
4 M High Speed Asynchronous CMOS SRAM with ECC, 512 K x 8, -40 to 85 degC, 36-Pin SOJ (SOJ-36), Pb-Free; Manufacturer: Integrated Silicon Solution Inc (ISSI); PartNumber: IS64WV5128EDBLL-10KLA1; Density: 4M; Organization: 512K x 8; Packing: Tray / Tube; Speed (ns): 10
footprint ISSI-SOJ-36_N (SOJ, 36-Leads, Body 23.62x10.29mm, Pitch 1.27mm, IPC Medium Density)
pins: 1 A0 (in) "Address Input", 2 A1 (in) "Address Input", 3 A2 (in) "Address Input", 4 A3 (in) "Address Input", 5 A4 (in) "Address Input", 6 ~{CE} (in) "Chip Enable Input", 7 I/O0 (io) "Bidirectional Port", 8 I/O1 (io) "Bidirectional Port", 9 VDD (power) "Power", 10 GND (power) "Ground", 11 I/O2 (io) "Bidirectional Port", 12 I/O3 (io) "Bidirectional Port", 13 ~{WE} (in) "Write Enable Input", 14 A5 (in) "Address Input", 15 A6 (in) "Address Input", 16 A7 (in) "Address Input", 17 A8 (in) "Address Input", 18 A9 (in) "Address Input", 19 NC "No Connection", 20 A10 (in) "Address Input", 21 A11 (in) "Address Input", 22 A12 (in) "Address Input", 23 A13 (in) "Address Input", 24 A14 (in) "Address Input", 25 I/O4 (io) "Bidirectional Port", 26 I/O5 (io) "Bidirectional Port", 27 VDD (power) "Power", 28 GND (power) "Ground", 29 I/O6 (io) "Bidirectional Port", 30 I/O7 (io) "Bidirectional Port", 31 ~{OE} (in) "Output Enable Input", 32 A15 (in) "Address Input", 33 A16 (in) "Address Input", 34 A17 (in) "Address Input", 35 A18 (in) "Address Input", 36 NC "No Connection"

## IS64WV5128EDBLL-10KLA1-TR
designator U?
4 M High Speed Asynchronous CMOS SRAM with ECC, 512 K x 8, -40 to 85 degC, 36-Pin SOJ (SOJ-36), Pb-Free; Manufacturer: Integrated Silicon Solution Inc (ISSI); PartNumber: IS64WV5128EDBLL-10KLA1-TR; Density: 4M; Organization: 512K x 8; Packing: Tape & Reel; Speed (ns): 10
footprint ISSI-SOJ-36_N (SOJ, 36-Leads, Body 23.62x10.29mm, Pitch 1.27mm, IPC Medium Density)
pins: 1 A0 (in) "Address Input", 2 A1 (in) "Address Input", 3 A2 (in) "Address Input", 4 A3 (in) "Address Input", 5 A4 (in) "Address Input", 6 ~{CE} (in) "Chip Enable Input", 7 I/O0 (io) "Bidirectional Port", 8 I/O1 (io) "Bidirectional Port", 9 VDD (power) "Power", 10 GND (power) "Ground", 11 I/O2 (io) "Bidirectional Port", 12 I/O3 (io) "Bidirectional Port", 13 ~{WE} (in) "Write Enable Input", 14 A5 (in) "Address Input", 15 A6 (in) "Address Input", 16 A7 (in) "Address Input", 17 A8 (in) "Address Input", 18 A9 (in) "Address Input", 19 NC "No Connection", 20 A10 (in) "Address Input", 21 A11 (in) "Address Input", 22 A12 (in) "Address Input", 23 A13 (in) "Address Input", 24 A14 (in) "Address Input", 25 I/O4 (io) "Bidirectional Port", 26 I/O5 (io) "Bidirectional Port", 27 VDD (power) "Power", 28 GND (power) "Ground", 29 I/O6 (io) "Bidirectional Port", 30 I/O7 (io) "Bidirectional Port", 31 ~{OE} (in) "Output Enable Input", 32 A15 (in) "Address Input", 33 A16 (in) "Address Input", 34 A17 (in) "Address Input", 35 A18 (in) "Address Input", 36 NC "No Connection"

## IS64WV5128EDBLL-10KLA3
designator U?
4 M High Speed Asynchronous CMOS SRAM with ECC, 512 K x 8, -40 to 125 degC, 36-Pin SOJ (SOJ-36), Pb-Free; Manufacturer: Integrated Silicon Solution Inc (ISSI); PartNumber: IS64WV5128EDBLL-10KLA3; Density: 4M; Organization: 512K x 8; Packing: Tray / Tube; Speed (ns): 10
footprint ISSI-SOJ-36_N (SOJ, 36-Leads, Body 23.62x10.29mm, Pitch 1.27mm, IPC Medium Density)
pins: 1 A0 (in) "Address Input", 2 A1 (in) "Address Input", 3 A2 (in) "Address Input", 4 A3 (in) "Address Input", 5 A4 (in) "Address Input", 6 ~{CE} (in) "Chip Enable Input", 7 I/O0 (io) "Bidirectional Port", 8 I/O1 (io) "Bidirectional Port", 9 VDD (power) "Power", 10 GND (power) "Ground", 11 I/O2 (io) "Bidirectional Port", 12 I/O3 (io) "Bidirectional Port", 13 ~{WE} (in) "Write Enable Input", 14 A5 (in) "Address Input", 15 A6 (in) "Address Input", 16 A7 (in) "Address Input", 17 A8 (in) "Address Input", 18 A9 (in) "Address Input", 19 NC "No Connection", 20 A10 (in) "Address Input", 21 A11 (in) "Address Input", 22 A12 (in) "Address Input", 23 A13 (in) "Address Input", 24 A14 (in) "Address Input", 25 I/O4 (io) "Bidirectional Port", 26 I/O5 (io) "Bidirectional Port", 27 VDD (power) "Power", 28 GND (power) "Ground", 29 I/O6 (io) "Bidirectional Port", 30 I/O7 (io) "Bidirectional Port", 31 ~{OE} (in) "Output Enable Input", 32 A15 (in) "Address Input", 33 A16 (in) "Address Input", 34 A17 (in) "Address Input", 35 A18 (in) "Address Input", 36 NC "No Connection"

## IS64WV5128EDBLL-10KLA3-TR
designator U?
4 M High Speed Asynchronous CMOS SRAM with ECC, 512 K x 8, -40 to 125 degC, 36-Pin SOJ (SOJ-36), Pb-Free; Manufacturer: Integrated Silicon Solution Inc (ISSI); PartNumber: IS64WV5128EDBLL-10KLA3-TR; Density: 4M; Organization: 512K x 8; Packing: Tape & Reel; Speed (ns): 10
footprint ISSI-SOJ-36_N (SOJ, 36-Leads, Body 23.62x10.29mm, Pitch 1.27mm, IPC Medium Density)
pins: 1 A0 (in) "Address Input", 2 A1 (in) "Address Input", 3 A2 (in) "Address Input", 4 A3 (in) "Address Input", 5 A4 (in) "Address Input", 6 ~{CE} (in) "Chip Enable Input", 7 I/O0 (io) "Bidirectional Port", 8 I/O1 (io) "Bidirectional Port", 9 VDD (power) "Power", 10 GND (power) "Ground", 11 I/O2 (io) "Bidirectional Port", 12 I/O3 (io) "Bidirectional Port", 13 ~{WE} (in) "Write Enable Input", 14 A5 (in) "Address Input", 15 A6 (in) "Address Input", 16 A7 (in) "Address Input", 17 A8 (in) "Address Input", 18 A9 (in) "Address Input", 19 NC "No Connection", 20 A10 (in) "Address Input", 21 A11 (in) "Address Input", 22 A12 (in) "Address Input", 23 A13 (in) "Address Input", 24 A14 (in) "Address Input", 25 I/O4 (io) "Bidirectional Port", 26 I/O5 (io) "Bidirectional Port", 27 VDD (power) "Power", 28 GND (power) "Ground", 29 I/O6 (io) "Bidirectional Port", 30 I/O7 (io) "Bidirectional Port", 31 ~{OE} (in) "Output Enable Input", 32 A15 (in) "Address Input", 33 A16 (in) "Address Input", 34 A17 (in) "Address Input", 35 A18 (in) "Address Input", 36 NC "No Connection"

## IS64WV10248BLL-10CTLA3
designator U?
8 M High Speed CMOS SRAM, 1 M x 8, -40 to 125 degC, 44-Pin SOP (TSOP-2-44), Pb-Free; Manufacturer: Integrated Silicon Solution Inc (ISSI); PartNumber: IS64WV10248BLL-10CTLA3; Organization: 1M x 8; Packing: Tray / Tube; Speed (ns): 10
footprint ISSI-TSOP-2-44_N (SOP, 44-Leads, Body 18.5x10.3mm, Pitch 0.8mm, IPC Medium Density)
part A pins: 3 A0 (in) "Address Input", 4 A1 (in) "Address Input", 5 A2 (in) "Address Input", 6 A3 (in) "Address Input", 7 A4 (in) "Address Input", 8 ~{CE} (in) "Chip Enable Input", 9 I/O0 (io) "Data Input / Output", 10 I/O1 (io) "Data Input / Output", 11 VDD (power) "Power", 12 GND (power) "Ground", 13 I/O2 (io) "Data Input / Output", 14 I/O3 (io) "Data Input / Output", 15 ~{WE} (in) "Write Enable Input", 16 A5 (in) "Address Input", 17 A6 (in) "Address Input", 18 A7 (in) "Address Input", 19 A8 (in) "Address Input", 20 A9 (in) "Address Input", 25 A19 (in) "Address Input", 26 A10 (in) "Address Input", 27 A11 (in) "Address Input", 28 A12 (in) "Address Input", 29 A13 (in) "Address Input", 30 A14 (in) "Address Input", 31 I/O4 (io) "Data Input / Output", 32 I/O5 (io) "Data Input / Output", 33 VDD (power) "Power", 34 GND (power) "Ground", 35 I/O6 (io) "Data Input / Output", 36 I/O7 (io) "Data Input / Output", 37 ~{OE} (in) "Output Enable Input", 38 A15 (in) "Address Input", 39 A16 (in) "Address Input", 40 A17 (in) "Address Input", 41 A18 (in) "Address Input"
part B pins: 1 NC "No Connection", 2 NC "No Connection", 21 NC "No Connection", 22 NC "No Connection", 23 NC "No Connection", 24 NC "No Connection", 42 NC "No Connection", 43 NC "No Connection", 44 NC "No Connection"

## IS64WV10248BLL-10CTLA3-TR
designator U?
8 M High Speed CMOS SRAM, 1 M x 8, -40 to 125 degC, 44-Pin SOP (TSOP-2-44), Pb-Free; Manufacturer: Integrated Silicon Solution Inc (ISSI); PartNumber: IS64WV10248BLL-10CTLA3-TR; Organization: 1M x 8; Packing: Tape & Reel; Speed (ns): 10
footprint ISSI-TSOP-2-44_N (SOP, 44-Leads, Body 18.5x10.3mm, Pitch 0.8mm, IPC Medium Density)
part A pins: 3 A0 (in) "Address Input", 4 A1 (in) "Address Input", 5 A2 (in) "Address Input", 6 A3 (in) "Address Input", 7 A4 (in) "Address Input", 8 ~{CE} (in) "Chip Enable Input", 9 I/O0 (io) "Data Input / Output", 10 I/O1 (io) "Data Input / Output", 11 VDD (power) "Power", 12 GND (power) "Ground", 13 I/O2 (io) "Data Input / Output", 14 I/O3 (io) "Data Input / Output", 15 ~{WE} (in) "Write Enable Input", 16 A5 (in) "Address Input", 17 A6 (in) "Address Input", 18 A7 (in) "Address Input", 19 A8 (in) "Address Input", 20 A9 (in) "Address Input", 25 A19 (in) "Address Input", 26 A10 (in) "Address Input", 27 A11 (in) "Address Input", 28 A12 (in) "Address Input", 29 A13 (in) "Address Input", 30 A14 (in) "Address Input", 31 I/O4 (io) "Data Input / Output", 32 I/O5 (io) "Data Input / Output", 33 VDD (power) "Power", 34 GND (power) "Ground", 35 I/O6 (io) "Data Input / Output", 36 I/O7 (io) "Data Input / Output", 37 ~{OE} (in) "Output Enable Input", 38 A15 (in) "Address Input", 39 A16 (in) "Address Input", 40 A17 (in) "Address Input", 41 A18 (in) "Address Input"
part B pins: 1 NC "No Connection", 2 NC "No Connection", 21 NC "No Connection", 22 NC "No Connection", 23 NC "No Connection", 24 NC "No Connection", 42 NC "No Connection", 43 NC "No Connection", 44 NC "No Connection"

## IS64WV10248BLL-10MA3
designator U?
8 M High Speed CMOS SRAM, 1 M x 8, -40 to 125 degC, 48-Pin BGA (TF-BGA-48); Manufacturer: Integrated Silicon Solution Inc (ISSI); PartNumber: IS64WV10248BLL-10MA3; Organization: 1M x 8; Packing: Tray / Tube; Speed (ns): 10
footprint ISSI-TF-BGA-48-9000x11000DE (BGA, 48-Balls, Body 11x9mm, Pitch 0.75mm)
part A pins: A2 ~{OE} (in) "Output Enable Input", A3 A0 (in) "Address Input", A4 A1 (in) "Address Input", A5 A2 (in) "Address Input", B3 A3 (in) "Address Input", B4 A4 (in) "Address Input", B5 ~{CE} (in) "Chip Enable Input", B6 I/O0 (io) "Data Input / Output", C3 A5 (in) "Address Input", C4 A6 (in) "Address Input", C5 I/O1 (io) "Data Input / Output", C6 I/O2 (io) "Data Input / Output", D1 GND (power) "Ground", D3 A17 (in) "Address Input", D4 A7 (in) "Address Input", D5 I/O3 (io) "Data Input / Output", D6 VDD (power) "Power", E1 VDD (power) "Power", E4 A16 (in) "Address Input", E5 I/O4 (io) "Data Input / Output", E6 GND (power) "Ground", F3 A14 (in) "Address Input", F4 A15 (in) "Address Input", F5 I/O5 (io) "Data Input / Output", F6 I/O6 (io) "Data Input / Output", G3 A12 (in) "Address Input", G4 A13 (in) "Address Input", G5 ~{WE} (in) "Write Enable Input", G6 I/O7 (io) "Data Input / Output", H1 A18 (in) "Address Input", H2 A8 (in) "Address Input", H3 A9 (in) "Address Input", H4 A10 (in) "Address Input", H5 A11 (in) "Address Input", H6 A19 (in) "Address Input"
part B pins: A1 NC "No Connection", A6 NC "No Connection", B1 NC "No Connection", B2 NC "No Connection", C1 NC "No Connection", C2 NC "No Connection", D2 NC "No Connection", E2 NC "No Connection", E3 NC "No Connection", F1 NC "No Connection", F2 NC "No Connection", G1 NC "No Connection", G2 NC "No Connection"

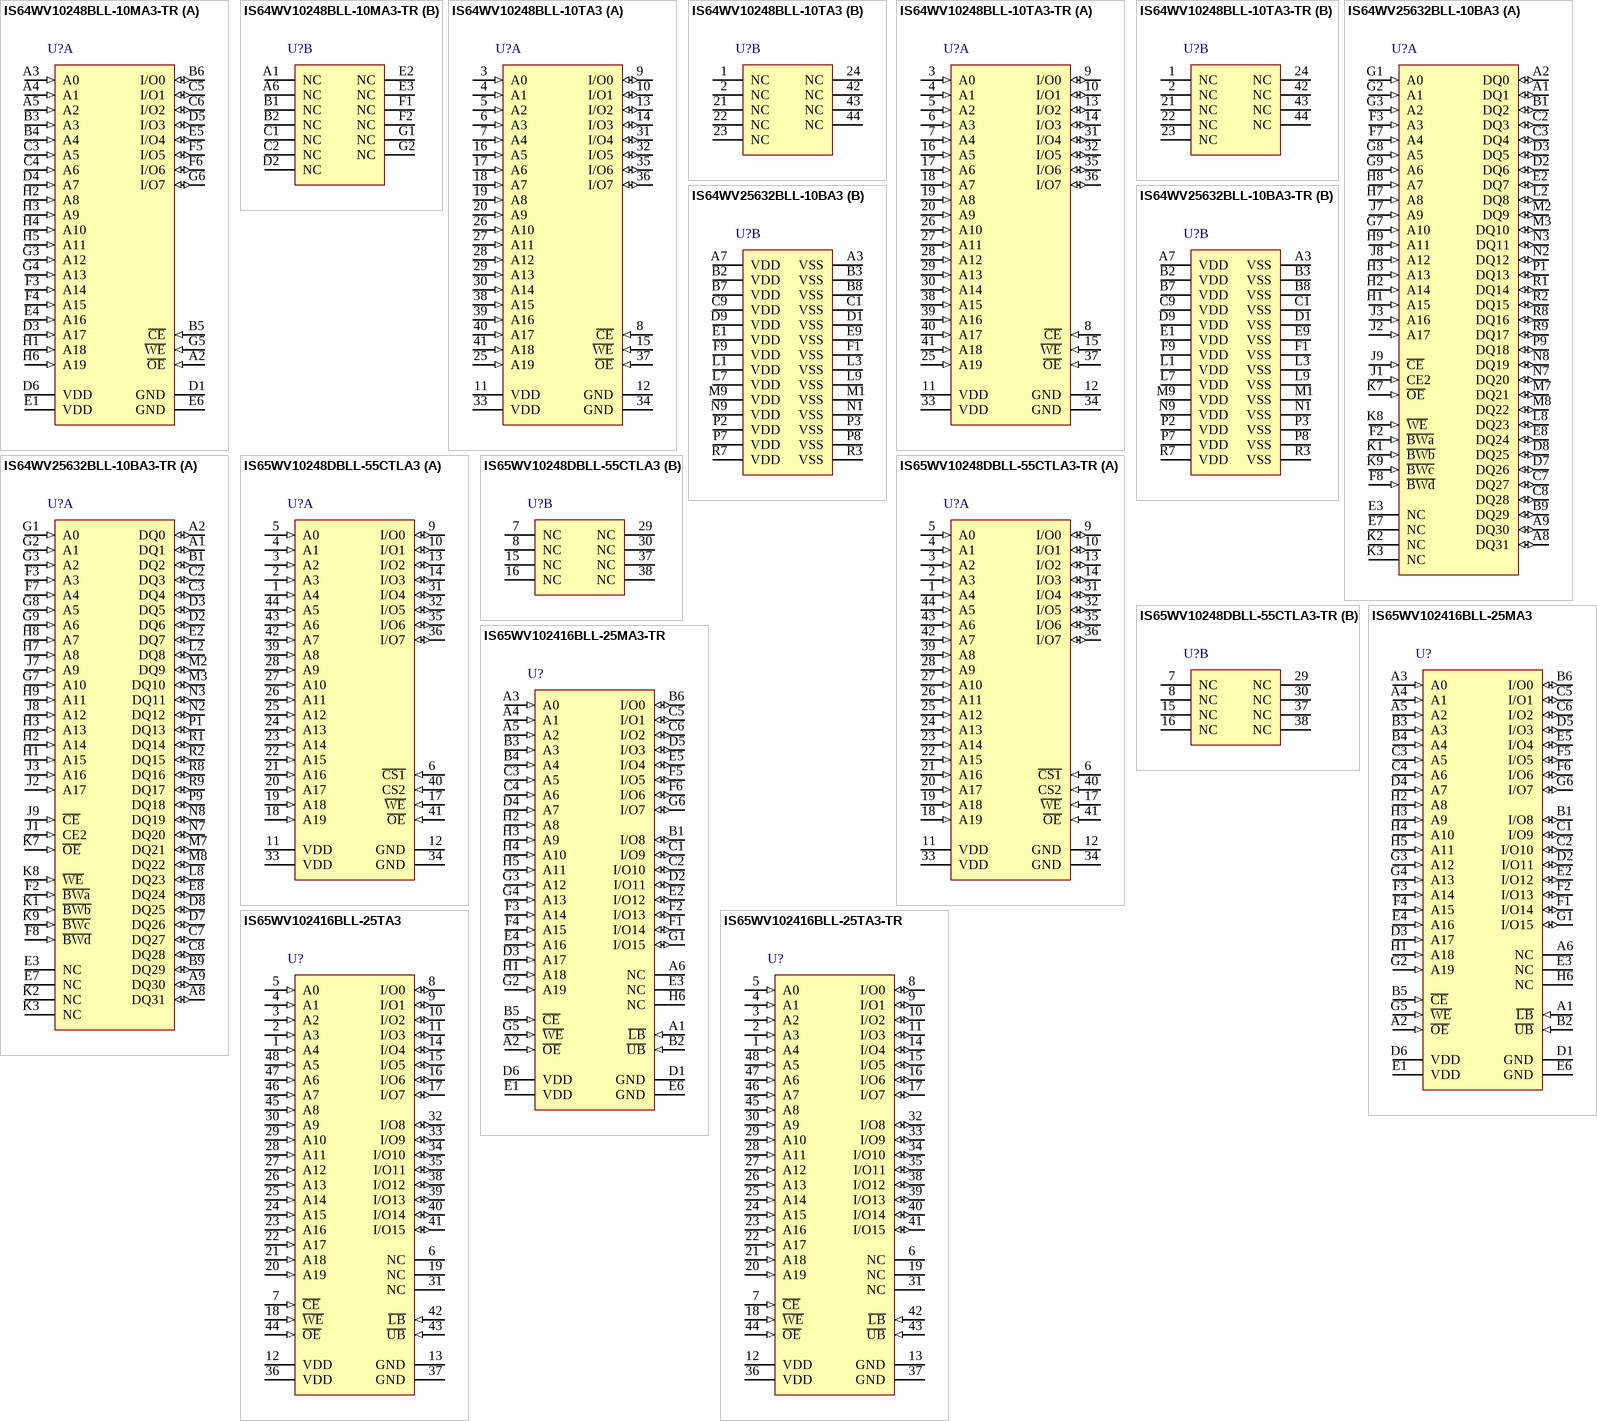
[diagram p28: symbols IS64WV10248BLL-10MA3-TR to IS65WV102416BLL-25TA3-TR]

## IS64WV10248BLL-10MA3-TR
designator U?
8 M High Speed CMOS SRAM, 1 M x 8, -40 to 125 degC, 48-Pin BGA (TF-BGA-48); Manufacturer: Integrated Silicon Solution Inc (ISSI); PartNumber: IS64WV10248BLL-10MA3-TR; Organization: 1M x 8; Packing: Tape & Reel; Speed (ns): 10
footprint ISSI-TF-BGA-48-9000x11000DE (BGA, 48-Balls, Body 11x9mm, Pitch 0.75mm)
part A pins: A2 ~{OE} (in) "Output Enable Input", A3 A0 (in) "Address Input", A4 A1 (in) "Address Input", A5 A2 (in) "Address Input", B3 A3 (in) "Address Input", B4 A4 (in) "Address Input", B5 ~{CE} (in) "Chip Enable Input", B6 I/O0 (io) "Data Input / Output", C3 A5 (in) "Address Input", C4 A6 (in) "Address Input", C5 I/O1 (io) "Data Input / Output", C6 I/O2 (io) "Data Input / Output", D1 GND (power) "Ground", D3 A17 (in) "Address Input", D4 A7 (in) "Address Input", D5 I/O3 (io) "Data Input / Output", D6 VDD (power) "Power", E1 VDD (power) "Power", E4 A16 (in) "Address Input", E5 I/O4 (io) "Data Input / Output", E6 GND (power) "Ground", F3 A14 (in) "Address Input", F4 A15 (in) "Address Input", F5 I/O5 (io) "Data Input / Output", F6 I/O6 (io) "Data Input / Output", G3 A12 (in) "Address Input", G4 A13 (in) "Address Input", G5 ~{WE} (in) "Write Enable Input", G6 I/O7 (io) "Data Input / Output", H1 A18 (in) "Address Input", H2 A8 (in) "Address Input", H3 A9 (in) "Address Input", H4 A10 (in) "Address Input", H5 A11 (in) "Address Input", H6 A19 (in) "Address Input"
part B pins: A1 NC "No Connection", A6 NC "No Connection", B1 NC "No Connection", B2 NC "No Connection", C1 NC "No Connection", C2 NC "No Connection", D2 NC "No Connection", E2 NC "No Connection", E3 NC "No Connection", F1 NC "No Connection", F2 NC "No Connection", G1 NC "No Connection", G2 NC "No Connection"

## IS64WV10248BLL-10TA3
designator U?
8 M High Speed CMOS SRAM, 1 M x 8, -40 to 125 degC, 44-Pin SOP (TSOP-2-44); Manufacturer: Integrated Silicon Solution Inc (ISSI); PartNumber: IS64WV10248BLL-10TA3; Organization: 1M x 8; Packing: Tray / Tube; Speed (ns): 10
footprint ISSI-TSOP-2-44_N (SOP, 44-Leads, Body 18.5x10.3mm, Pitch 0.8mm, IPC Medium Density)
part A pins: 3 A0 (in) "Address Input", 4 A1 (in) "Address Input", 5 A2 (in) "Address Input", 6 A3 (in) "Address Input", 7 A4 (in) "Address Input", 8 ~{CE} (in) "Chip Enable Input", 9 I/O0 (io) "Data Input / Output", 10 I/O1 (io) "Data Input / Output", 11 VDD (power) "Power", 12 GND (power) "Ground", 13 I/O2 (io) "Data Input / Output", 14 I/O3 (io) "Data Input / Output", 15 ~{WE} (in) "Write Enable Input", 16 A5 (in) "Address Input", 17 A6 (in) "Address Input", 18 A7 (in) "Address Input", 19 A8 (in) "Address Input", 20 A9 (in) "Address Input", 25 A19 (in) "Address Input", 26 A10 (in) "Address Input", 27 A11 (in) "Address Input", 28 A12 (in) "Address Input", 29 A13 (in) "Address Input", 30 A14 (in) "Address Input", 31 I/O4 (io) "Data Input / Output", 32 I/O5 (io) "Data Input / Output", 33 VDD (power) "Power", 34 GND (power) "Ground", 35 I/O6 (io) "Data Input / Output", 36 I/O7 (io) "Data Input / Output", 37 ~{OE} (in) "Output Enable Input", 38 A15 (in) "Address Input", 39 A16 (in) "Address Input", 40 A17 (in) "Address Input", 41 A18 (in) "Address Input"
part B pins: 1 NC "No Connection", 2 NC "No Connection", 21 NC "No Connection", 22 NC "No Connection", 23 NC "No Connection", 24 NC "No Connection", 42 NC "No Connection", 43 NC "No Connection", 44 NC "No Connection"

## IS64WV10248BLL-10TA3-TR
designator U?
8 M High Speed CMOS SRAM, 1 M x 8, -40 to 125 degC, 44-Pin SOP (TSOP-2-44); Manufacturer: Integrated Silicon Solution Inc (ISSI); PartNumber: IS64WV10248BLL-10TA3-TR; Organization: 1M x 8; Packing: Tape & Reel; Speed (ns): 10
footprint ISSI-TSOP-2-44_N (SOP, 44-Leads, Body 18.5x10.3mm, Pitch 0.8mm, IPC Medium Density)
part A pins: 3 A0 (in) "Address Input", 4 A1 (in) "Address Input", 5 A2 (in) "Address Input", 6 A3 (in) "Address Input", 7 A4 (in) "Address Input", 8 ~{CE} (in) "Chip Enable Input", 9 I/O0 (io) "Data Input / Output", 10 I/O1 (io) "Data Input / Output", 11 VDD (power) "Power", 12 GND (power) "Ground", 13 I/O2 (io) "Data Input / Output", 14 I/O3 (io) "Data Input / Output", 15 ~{WE} (in) "Write Enable Input", 16 A5 (in) "Address Input", 17 A6 (in) "Address Input", 18 A7 (in) "Address Input", 19 A8 (in) "Address Input", 20 A9 (in) "Address Input", 25 A19 (in) "Address Input", 26 A10 (in) "Address Input", 27 A11 (in) "Address Input", 28 A12 (in) "Address Input", 29 A13 (in) "Address Input", 30 A14 (in) "Address Input", 31 I/O4 (io) "Data Input / Output", 32 I/O5 (io) "Data Input / Output", 33 VDD (power) "Power", 34 GND (power) "Ground", 35 I/O6 (io) "Data Input / Output", 36 I/O7 (io) "Data Input / Output", 37 ~{OE} (in) "Output Enable Input", 38 A15 (in) "Address Input", 39 A16 (in) "Address Input", 40 A17 (in) "Address Input", 41 A18 (in) "Address Input"
part B pins: 1 NC "No Connection", 2 NC "No Connection", 21 NC "No Connection", 22 NC "No Connection", 23 NC "No Connection", 24 NC "No Connection", 42 NC "No Connection", 43 NC "No Connection", 44 NC "No Connection"

## IS64WV25632BLL-10BA3
designator U?
8 M High Speed Asynchronous CMOS SRAM with 3.3 V Supply, 256 K x 32, -40 to 125 degC, 90-Pin BGA (TF-BGA-90); Manufacturer: Integrated Silicon Solution Inc (ISSI); PartNumber: IS64WV25632BLL-10BA3; Density: 8M; Packing: Tray / Tube; Speed (ns): 10
footprint ISSI-TF-BGA-90-8000X13000DE (BGA, 90-Balls, Body 13x8mm, Pitch 0.8mm)
part A pins: A1 DQ1 (io) "Data I/O", A2 DQ0 (io) "Data I/O", A8 DQ31 (io) "Data I/O", A9 DQ30 (io) "Data I/O", B1 DQ2 (io) "Data I/O", B9 DQ29 (io) "Data I/O", C2 DQ3 (io) "Data I/O", C3 DQ4 (io) "Data I/O", C7 DQ27 (io) "Data I/O", C8 DQ28 (io) "Data I/O", D2 DQ6 (io) "Data I/O", D3 DQ5 (io) "Data I/O", D7 DQ26 (io) "Data I/O", D8 DQ25 (io) "Data I/O", E2 DQ7 (io) "Data I/O", E3 NC "No Connection", E7 NC "No Connection", E8 DQ24 (io) "Data I/O", F2 ~{BWa} (in) "Byte Write Control", F3 A3 (in) "Address Inputs", F7 A4 (in) "Address Inputs", F8 ~{BWd} (in) "Byte Write Control", G1 A0 (in) "Address Inputs", G2 A1 (in) "Address Inputs", G3 A2 (in) "Address Inputs", G7 A10 (in) "Address Inputs", G8 A5 (in) "Address Inputs", G9 A6 (in) "Address Inputs", H1 A15 (in) "Address Inputs", H2 A14 (in) "Address Inputs", H3 A13 (in) "Address Inputs", H7 A8 (in) "Address Inputs", H8 A7 (in) "Address Inputs", H9 A11 (in) "Address Inputs", J1 CE2 (in) "Chip Enable Input", J2 A17 (in) "Address Inputs", J3 A16 (in) "Address Inputs", J7 A9 (in) "Address Inputs", J8 A12 (in) "Address Inputs", J9 ~{CE} (in) "Chip Enable Input", K1 ~{BWb} (in) "Byte Write Control", K2 NC "No Connection", K3 NC "No Connection", K7 ~{OE} (in) "Output Enable Input", K8 ~{WE} (in) "Write Enable Input", K9 ~{BWc} (in) "Byte Write Control", L2 DQ8 (io) "Data I/O", L8 DQ23 (io) "Data I/O", M2 DQ9 (io) "Data I/O", M3 DQ10 (io) "Data I/O", M7 DQ21 (io) "Data I/O", M8 DQ22 (io) "Data I/O", N2 DQ12 (io) "Data I/O", N3 DQ11 (io) "Data I/O", N7 DQ20 (io) "Data I/O", N8 DQ19 (io) "Data I/O", P1 DQ13 (io) "Data I/O", P9 DQ18 (io) "Data I/O", R1 DQ14 (io) "Data I/O", R2 DQ15 (io) "Data I/O", R8 DQ16 (io) "Data I/O", R9 DQ17 (io) "Data I/O"
part B pins: A3 VSS (power) "Ground", A7 VDD (power) "Power", B2 VDD (power) "Power", B3 VSS (power) "Ground", B7 VDD (power) "Power", B8 VSS (power) "Ground", C1 VSS (power) "Ground", C9 VDD (power) "Power", D1 VSS (power) "Ground", D9 VDD (power) "Power", E1 VDD (power) "Power", E9 VSS (power) "Ground", F1 VSS (power) "Ground", F9 VDD (power) "Power", L1 VDD (power) "Power", L3 VSS (power) "Ground", L7 VDD (power) "Power", L9 VSS (power) "Ground", M1 VSS (power) "Ground", M9 VDD (power) "Power", N1 VSS (power) "Ground", N9 VDD (power) "Power", P2 VDD (power) "Power", P3 VSS (power) "Ground", P7 VDD (power) "Power", P8 VSS (power) "Ground", R3 VSS (power) "Ground", R7 VDD (power) "Power"

## IS64WV25632BLL-10BA3-TR
designator U?
8 M High Speed Asynchronous CMOS SRAM with 3.3 V Supply, 256 K x 32, -40 to 125 degC, 90-Pin BGA (TF-BGA-90); Manufacturer: Integrated Silicon Solution Inc (ISSI); PartNumber: IS64WV25632BLL-10BA3-TR; Density: 8M; Packing: Tape & Reel; Speed (ns): 10
footprint ISSI-TF-BGA-90-8000X13000DE (BGA, 90-Balls, Body 13x8mm, Pitch 0.8mm)
part A pins: A1 DQ1 (io) "Data I/O", A2 DQ0 (io) "Data I/O", A8 DQ31 (io) "Data I/O", A9 DQ30 (io) "Data I/O", B1 DQ2 (io) "Data I/O", B9 DQ29 (io) "Data I/O", C2 DQ3 (io) "Data I/O", C3 DQ4 (io) "Data I/O", C7 DQ27 (io) "Data I/O", C8 DQ28 (io) "Data I/O", D2 DQ6 (io) "Data I/O", D3 DQ5 (io) "Data I/O", D7 DQ26 (io) "Data I/O", D8 DQ25 (io) "Data I/O", E2 DQ7 (io) "Data I/O", E3 NC "No Connection", E7 NC "No Connection", E8 DQ24 (io) "Data I/O", F2 ~{BWa} (in) "Byte Write Control", F3 A3 (in) "Address Inputs", F7 A4 (in) "Address Inputs", F8 ~{BWd} (in) "Byte Write Control", G1 A0 (in) "Address Inputs", G2 A1 (in) "Address Inputs", G3 A2 (in) "Address Inputs", G7 A10 (in) "Address Inputs", G8 A5 (in) "Address Inputs", G9 A6 (in) "Address Inputs", H1 A15 (in) "Address Inputs", H2 A14 (in) "Address Inputs", H3 A13 (in) "Address Inputs", H7 A8 (in) "Address Inputs", H8 A7 (in) "Address Inputs", H9 A11 (in) "Address Inputs", J1 CE2 (in) "Chip Enable Input", J2 A17 (in) "Address Inputs", J3 A16 (in) "Address Inputs", J7 A9 (in) "Address Inputs", J8 A12 (in) "Address Inputs", J9 ~{CE} (in) "Chip Enable Input", K1 ~{BWb} (in) "Byte Write Control", K2 NC "No Connection", K3 NC "No Connection", K7 ~{OE} (in) "Output Enable Input", K8 ~{WE} (in) "Write Enable Input", K9 ~{BWc} (in) "Byte Write Control", L2 DQ8 (io) "Data I/O", L8 DQ23 (io) "Data I/O", M2 DQ9 (io) "Data I/O", M3 DQ10 (io) "Data I/O", M7 DQ21 (io) "Data I/O", M8 DQ22 (io) "Data I/O", N2 DQ12 (io) "Data I/O", N3 DQ11 (io) "Data I/O", N7 DQ20 (io) "Data I/O", N8 DQ19 (io) "Data I/O", P1 DQ13 (io) "Data I/O", P9 DQ18 (io) "Data I/O", R1 DQ14 (io) "Data I/O", R2 DQ15 (io) "Data I/O", R8 DQ16 (io) "Data I/O", R9 DQ17 (io) "Data I/O"
part B pins: A3 VSS (power) "Ground", A7 VDD (power) "Power", B2 VDD (power) "Power", B3 VSS (power) "Ground", B7 VDD (power) "Power", B8 VSS (power) "Ground", C1 VSS (power) "Ground", C9 VDD (power) "Power", D1 VSS (power) "Ground", D9 VDD (power) "Power", E1 VDD (power) "Power", E9 VSS (power) "Ground", F1 VSS (power) "Ground", F9 VDD (power) "Power", L1 VDD (power) "Power", L3 VSS (power) "Ground", L7 VDD (power) "Power", L9 VSS (power) "Ground", M1 VSS (power) "Ground", M9 VDD (power) "Power", N1 VSS (power) "Ground", N9 VDD (power) "Power", P2 VDD (power) "Power", P3 VSS (power) "Ground", P7 VDD (power) "Power", P8 VSS (power) "Ground", R3 VSS (power) "Ground", R7 VDD (power) "Power"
